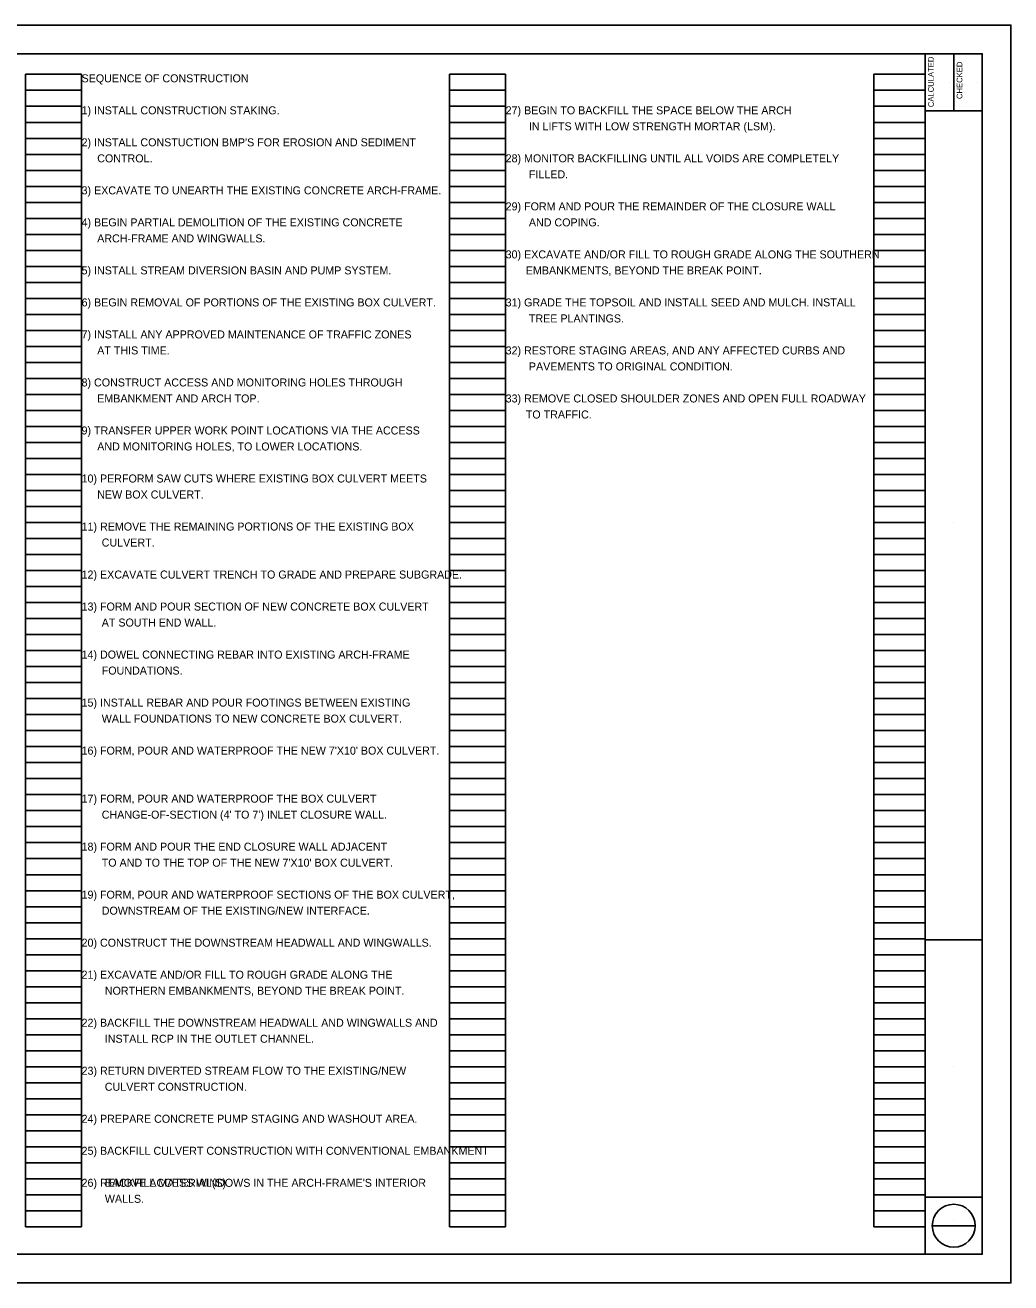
# Model space of a CAD drawing. Extents: x 0 to 55.9, y -18.9 to 33.1.
# Drawn here: x 16.75 to 34, y 0 to 22 of the extents above; entities that cross this region are included whole.
import ezdxf

# ---------------------------------------------------------------- set-up
doc = ezdxf.new("R2010")
doc.units = 0
for name, color, linetype in [('SC_Scratch1', 7, 'Continuous'), ('SH_Border', 7, 'Continuous'), ('SH_Cut_Line', 7, 'Continuous'), ('SH_Data', 7, 'Continuous'), ('SH_Text', 7, 'Continuous')]:
    doc.layers.add(name, color=color, linetype=linetype)

msp = doc.modelspace()

# ---------------------------------------------------------------- linework, layer by layer
at = {"layer": 'SC_Scratch1'}
for p, q in [((16.76, 0.98), (16.76, 21.14)), ((16.76, 21.14), (17.74, 21.14)), ((17.74, 0.98), (17.74, 21.14)), ((24.18, 0.98), (24.18, 21.14)), ((24.18, 21.14), (25.16, 21.14)), ((25.16, 0.98), (25.16, 21.14)), ((31.6, 0.98), (31.6, 21.14)), ((31.6, 21.14), (32.5, 21.14)), ((32.5, 0.98), (32.5, 21.14)), ((16.76, 20.86), (17.74, 20.86)), ((24.18, 20.86), (25.16, 20.86)), ((31.6, 20.86), (32.5, 20.86)), ((16.76, 20.58), (17.74, 20.58)), ((24.18, 20.58), (25.16, 20.58)), ((31.6, 20.58), (32.5, 20.58)), ((16.76, 20.3), (17.74, 20.3)), ((24.18, 20.3), (25.16, 20.3)), ((31.6, 20.3), (32.5, 20.3)), ((16.76, 20.02), (17.74, 20.02)), ((24.18, 20.02), (25.16, 20.02)), ((31.6, 20.02), (32.5, 20.02)), ((16.76, 19.74), (17.74, 19.74)), ((24.18, 19.74), (25.16, 19.74)), ((31.6, 19.74), (32.5, 19.74)), ((16.76, 19.46), (17.74, 19.46)), ((24.18, 19.46), (25.16, 19.46)), ((31.6, 19.46), (32.5, 19.46)), ((16.76, 19.18), (17.74, 19.18)), ((24.18, 19.18), (25.16, 19.18)), ((31.6, 19.18), (32.5, 19.18)), ((16.76, 18.9), (17.74, 18.9)), ((24.18, 18.9), (25.16, 18.9)), ((31.6, 18.9), (32.5, 18.9)), ((16.76, 18.62), (17.74, 18.62)), ((24.18, 18.62), (25.16, 18.62)), ((31.6, 18.62), (32.5, 18.62)), ((16.76, 18.34), (17.74, 18.34)), ((24.18, 18.34), (25.16, 18.34)), ((31.6, 18.34), (32.5, 18.34)), ((16.76, 18.06), (17.74, 18.06)), ((24.18, 18.06), (25.16, 18.06)), ((31.6, 18.06), (32.5, 18.06)), ((16.76, 17.78), (17.74, 17.78)), ((24.18, 17.78), (25.16, 17.78)), ((31.6, 17.78), (32.5, 17.78)), ((16.76, 17.5), (17.74, 17.5)), ((24.18, 17.5), (25.16, 17.5)), ((31.6, 17.5), (32.5, 17.5)), ((16.76, 17.22), (17.74, 17.22)), ((24.18, 17.22), (25.16, 17.22)), ((31.6, 17.22), (32.5, 17.22)), ((16.76, 16.94), (17.74, 16.94)), ((24.18, 16.94), (25.16, 16.94)), ((31.6, 16.94), (32.5, 16.94)), ((16.76, 16.66), (17.74, 16.66)), ((24.18, 16.66), (25.16, 16.66)), ((31.6, 16.66), (32.5, 16.66)), ((16.76, 16.38), (17.74, 16.38)), ((24.18, 16.38), (25.16, 16.38)), ((31.6, 16.38), (32.5, 16.38)), ((16.76, 16.1), (17.74, 16.1)), ((24.18, 16.1), (25.16, 16.1)), ((31.6, 16.1), (32.5, 16.1)), ((16.76, 15.82), (17.74, 15.82)), ((24.18, 15.82), (25.16, 15.82)), ((31.6, 15.82), (32.5, 15.82)), ((16.76, 15.54), (17.74, 15.54)), ((24.18, 15.54), (25.16, 15.54)), ((31.6, 15.54), (32.5, 15.54)), ((16.76, 15.26), (17.74, 15.26)), ((24.18, 15.26), (25.16, 15.26)), ((31.6, 15.26), (32.5, 15.26)), ((16.76, 14.98), (17.74, 14.98)), ((24.18, 14.98), (25.16, 14.98)), ((31.6, 14.98), (32.5, 14.98)), ((16.76, 14.7), (17.74, 14.7)), ((24.18, 14.7), (25.16, 14.7)), ((31.6, 14.7), (32.5, 14.7)), ((16.76, 14.42), (17.74, 14.42)), ((24.18, 14.42), (25.16, 14.42)), ((31.6, 14.42), (32.5, 14.42)), ((16.76, 14.14), (17.74, 14.14)), ((24.18, 14.14), (25.16, 14.14)), ((31.6, 14.14), (32.5, 14.14)), ((16.76, 13.86), (17.74, 13.86)), ((24.18, 13.86), (25.16, 13.86)), ((31.6, 13.86), (32.5, 13.86)), ((16.76, 13.58), (17.74, 13.58)), ((24.18, 13.58), (25.16, 13.58)), ((31.6, 13.58), (32.5, 13.58)), ((16.76, 13.3), (17.74, 13.3)), ((24.18, 13.3), (25.16, 13.3)), ((31.6, 13.3), (32.5, 13.3)), ((16.76, 13.02), (17.74, 13.02)), ((24.18, 13.02), (25.16, 13.02)), ((31.6, 13.02), (32.5, 13.02)), ((16.76, 12.74), (17.74, 12.74)), ((24.18, 12.74), (25.16, 12.74)), ((31.6, 12.74), (32.5, 12.74)), ((16.76, 12.46), (17.74, 12.46)), ((24.18, 12.46), (25.16, 12.46)), ((31.6, 12.46), (32.5, 12.46)), ((16.76, 12.18), (17.74, 12.18)), ((24.18, 12.18), (25.16, 12.18)), ((31.6, 12.18), (32.5, 12.18)), ((16.76, 11.9), (17.74, 11.9)), ((24.18, 11.9), (25.16, 11.9)), ((31.6, 11.9), (32.5, 11.9)), ((16.76, 11.62), (17.74, 11.62)), ((24.18, 11.62), (25.16, 11.62)), ((31.6, 11.62), (32.5, 11.62)), ((16.76, 11.34), (17.74, 11.34)), ((24.18, 11.34), (25.16, 11.34)), ((31.6, 11.34), (32.5, 11.34)), ((16.76, 11.06), (17.74, 11.06)), ((24.18, 11.06), (25.16, 11.06)), ((31.6, 11.06), (32.5, 11.06)), ((16.76, 10.78), (17.74, 10.78)), ((24.18, 10.78), (25.16, 10.78)), ((31.6, 10.78), (32.5, 10.78)), ((16.76, 10.5), (17.74, 10.5)), ((24.18, 10.5), (25.16, 10.5)), ((31.6, 10.5), (32.5, 10.5)), ((16.76, 10.22), (17.74, 10.22)), ((24.18, 10.22), (25.16, 10.22)), ((31.6, 10.22), (32.5, 10.22)), ((16.76, 9.94), (17.74, 9.94)), ((24.18, 9.94), (25.16, 9.94)), ((31.6, 9.94), (32.5, 9.94)), ((16.76, 9.66), (17.74, 9.66)), ((24.18, 9.66), (25.16, 9.66)), ((31.6, 9.66), (32.5, 9.66)), ((16.76, 9.38), (17.74, 9.38)), ((24.18, 9.38), (25.16, 9.38)), ((31.6, 9.38), (32.5, 9.38)), ((16.76, 9.1), (17.74, 9.1)), ((24.18, 9.1), (25.16, 9.1)), ((31.6, 9.1), (32.5, 9.1)), ((16.76, 8.82), (17.74, 8.82)), ((24.18, 8.82), (25.16, 8.82)), ((31.6, 8.82), (32.5, 8.82)), ((16.76, 8.54), (17.74, 8.54)), ((24.18, 8.54), (25.16, 8.54)), ((31.6, 8.54), (32.5, 8.54)), ((16.76, 8.26), (17.74, 8.26)), ((24.18, 8.26), (25.16, 8.26)), ((31.6, 8.26), (32.5, 8.26)), ((16.76, 7.98), (17.74, 7.98)), ((24.18, 7.98), (25.16, 7.98)), ((31.6, 7.98), (32.5, 7.98)), ((16.76, 7.7), (17.74, 7.7)), ((24.18, 7.7), (25.16, 7.7)), ((31.6, 7.7), (32.5, 7.7)), ((16.76, 7.42), (17.74, 7.42)), ((24.18, 7.42), (25.16, 7.42)), ((31.6, 7.42), (32.5, 7.42)), ((16.76, 7.14), (17.74, 7.14)), ((24.18, 7.14), (25.16, 7.14)), ((31.6, 7.14), (32.5, 7.14)), ((16.76, 6.86), (17.74, 6.86)), ((24.18, 6.86), (25.16, 6.86)), ((31.6, 6.86), (32.5, 6.86)), ((16.76, 6.58), (17.74, 6.58)), ((24.18, 6.58), (25.16, 6.58)), ((31.6, 6.58), (32.5, 6.58)), ((16.76, 6.3), (17.74, 6.3)), ((24.18, 6.3), (25.16, 6.3)), ((31.6, 6.3), (32.5, 6.3)), ((16.76, 6.02), (17.74, 6.02)), ((24.18, 6.02), (25.16, 6.02)), ((31.6, 6.02), (32.5, 6.02)), ((16.76, 5.74), (17.74, 5.74)), ((24.18, 5.74), (25.16, 5.74)), ((31.6, 5.74), (32.5, 5.74)), ((16.76, 5.46), (17.74, 5.46)), ((24.18, 5.46), (25.16, 5.46)), ((31.6, 5.46), (32.5, 5.46)), ((16.76, 5.18), (17.74, 5.18)), ((24.18, 5.18), (25.16, 5.18)), ((31.6, 5.18), (32.5, 5.18)), ((16.76, 4.9), (17.74, 4.9)), ((24.18, 4.9), (25.16, 4.9)), ((31.6, 4.9), (32.5, 4.9)), ((16.76, 4.62), (17.74, 4.62)), ((24.18, 4.62), (25.16, 4.62)), ((31.6, 4.62), (32.5, 4.62)), ((16.76, 4.34), (17.74, 4.34)), ((24.18, 4.34), (25.16, 4.34)), ((31.6, 4.34), (32.5, 4.34)), ((16.76, 4.06), (17.74, 4.06)), ((24.18, 4.06), (25.16, 4.06)), ((31.6, 4.06), (32.5, 4.06)), ((16.76, 3.78), (17.74, 3.78)), ((24.18, 3.78), (25.16, 3.78)), ((31.6, 3.78), (32.5, 3.78)), ((16.76, 3.5), (17.74, 3.5)), ((24.18, 3.5), (25.16, 3.5)), ((31.6, 3.5), (32.5, 3.5)), ((16.76, 3.22), (17.74, 3.22)), ((24.18, 3.22), (25.16, 3.22)), ((31.6, 3.22), (32.5, 3.22)), ((16.76, 2.94), (17.74, 2.94)), ((24.18, 2.94), (25.16, 2.94)), ((31.6, 2.94), (32.5, 2.94)), ((16.76, 2.66), (17.74, 2.66)), ((24.18, 2.66), (25.16, 2.66)), ((31.6, 2.66), (32.5, 2.66)), ((16.76, 2.38), (17.74, 2.38)), ((24.18, 2.38), (25.16, 2.38)), ((31.6, 2.38), (32.5, 2.38)), ((16.76, 2.1), (17.74, 2.1)), ((24.18, 2.1), (25.16, 2.1)), ((31.6, 2.1), (32.5, 2.1)), ((16.76, 1.82), (17.74, 1.82)), ((24.18, 1.82), (25.16, 1.82)), ((31.6, 1.82), (32.5, 1.82)), ((16.76, 1.54), (17.74, 1.54)), ((24.18, 1.54), (25.16, 1.54)), ((31.6, 1.54), (32.5, 1.54)), ((16.76, 1.26), (17.74, 1.26)), ((24.18, 1.26), (25.16, 1.26)), ((31.6, 1.26), (32.5, 1.26)), ((16.76, 0.98), (17.74, 0.98)), ((24.18, 0.98), (25.16, 0.98)), ((31.6, 0.98), (32.5, 0.98))]:
    msp.add_line(p, q, dxfattribs=at)
at = {"layer": 'SH_Border'}
for p, q in [((32.5, 0.5), (32.5, 21.5)), ((33, 21.5), (33, 20.5)), ((32.5, 20.5), (33.5, 20.5)), ((32.5, 6), (33.5, 6)), ((32.5, 1.5), (33.5, 1.5))]:
    msp.add_line(p, q, dxfattribs=at)
msp.add_lwpolyline([(2, 21.5), (33.5, 21.5), (33.5, 0.5), (2, 0.5)], close=True, dxfattribs=at)
at = {"layer": 'SH_Cut_Line'}
msp.add_lwpolyline([(0, 0), (34, 0), (34, 22), (0, 22)], close=True, dxfattribs=at)
at = {"layer": 'SH_Data'}
for p, q in [((32.92, 21.004), (32.92, 21.004)), ((33.42, 21.004), (33.42, 21.004)), ((33, 13.292), (33, 13.292)), ((33, 3.792), (33, 3.792)), ((32.625, 1), (33.375, 1)), ((33, 1.085), (33, 1.085)), ((33, 0.745), (33, 0.745))]:
    msp.add_line(p, q, dxfattribs=at)
msp.add_circle((33, 1), 0.375, dxfattribs=at)

# ---------------------------------------------------------------- texts
for s, p in [('CALCULATED', (32.652, 20.565)), ('CHECKED', (33.152, 20.708))]:
    msp.add_text(s, height=0.1, rotation=90, dxfattribs=at).set_placement(p)
at = {"layer": 'SH_Text'}
for s, p in [('SEQUENCE OF CONSTRUCTION', (17.74, 21)), ('1) INSTALL CONSTRUCTION STAKING.', (17.74, 20.44)), ('27) BEGIN TO BACKFILL THE SPACE BELOW THE ARCH', (25.16, 20.44)), ('IN LIFTS WITH LOW STRENGTH MORTAR (LSM).', (25.567, 20.16)), ("2) INSTALL CONSTUCTION BMP'S FOR EROSION AND SEDIMENT ", (17.74, 19.88)), ('CONTROL.', (18.014, 19.6)), ('28) MONITOR BACKFILLING UNTIL ALL VOIDS ARE COMPLETELY ', (25.16, 19.6)), ('FILLED.', (25.567, 19.32)), ('3) EXCAVATE TO UNEARTH THE EXISTING CONCRETE ARCH-FRAME.', (17.74, 19.04)), ('29) FORM AND POUR THE REMAINDER OF THE CLOSURE WALL', (25.16, 18.76)), ('4) BEGIN PARTIAL DEMOLITION OF THE EXISTING CONCRETE', (17.74, 18.48)), ('AND COPING.', (25.567, 18.48)), ('ARCH-FRAME AND WINGWALLS.', (18.014, 18.2)), ('30) EXCAVATE AND/OR FILL TO ROUGH GRADE ALONG THE SOUTHERN ', (25.16, 17.92)), ('5) INSTALL STREAM DIVERSION BASIN AND PUMP SYSTEM.', (17.74, 17.64)), ('EMBANKMENTS, BEYOND THE BREAK POINT.', (25.513, 17.64)), ('6) BEGIN REMOVAL OF PORTIONS OF THE EXISTING BOX CULVERT.', (17.74, 17.08)), ('31) GRADE THE TOPSOIL AND INSTALL SEED AND MULCH. INSTALL', (25.16, 17.08)), ('TREE PLANTINGS.', (25.567, 16.8)), ('7) INSTALL ANY APPROVED MAINTENANCE OF TRAFFIC ZONES', (17.74, 16.52)), ('AT THIS TIME.', (18.014, 16.24)), ('32) RESTORE STAGING AREAS, AND ANY AFFECTED CURBS AND', (25.16, 16.24)), ('PAVEMENTS TO ORIGINAL CONDITION.', (25.567, 15.96)), ('8) CONSTRUCT ACCESS AND MONITORING HOLES THROUGH ', (17.74, 15.68)), ('EMBANKMENT AND ARCH TOP.', (18.014, 15.4)), ('33) REMOVE CLOSED SHOULDER ZONES AND OPEN FULL ROADWAY', (25.16, 15.4)), ('TO TRAFFIC.', (25.513, 15.12)), ('9) TRANSFER UPPER WORK POINT LOCATIONS VIA THE ACCESS', (17.74, 14.84)), ('AND MONITORING HOLES, TO LOWER LOCATIONS.', (18.014, 14.56)), ('10) PERFORM SAW CUTS WHERE EXISTING BOX CULVERT MEETS', (17.74, 14)), ('NEW BOX CULVERT.', (18.014, 13.72)), ('11) REMOVE THE REMAINING PORTIONS OF THE EXISTING BOX ', (17.74, 13.16)), ('CULVERT.', (18.093, 12.88)), ('12) EXCAVATE CULVERT TRENCH TO GRADE AND PREPARE SUBGRADE.', (17.74, 12.32)), ('13) FORM AND POUR SECTION OF NEW CONCRETE BOX CULVERT', (17.74, 11.76)), ('AT SOUTH END WALL.', (18.093, 11.48)), ('14) DOWEL CONNECTING REBAR INTO EXISTING ARCH-FRAME', (17.74, 10.92)), ('FOUNDATIONS.', (18.093, 10.64)), ('15) INSTALL REBAR AND POUR FOOTINGS BETWEEN EXISTING', (17.74, 10.08)), ('WALL FOUNDATIONS TO NEW CONCRETE BOX CULVERT.', (18.093, 9.8)), ("16) FORM, POUR AND WATERPROOF THE NEW 7'X10' BOX CULVERT.", (17.74, 9.24)), ('17) FORM, POUR AND WATERPROOF THE BOX CULVERT ', (17.74, 8.4)), ("CHANGE-OF-SECTION (4' TO 7') INLET CLOSURE WALL.", (18.093, 8.12)), ('18) FORM AND POUR THE END CLOSURE WALL ADJACENT', (17.74, 7.56)), ("TO AND TO THE TOP OF THE NEW 7'X10' BOX CULVERT.", (18.093, 7.28)), ('19) FORM, POUR AND WATERPROOF SECTIONS OF THE BOX CULVERT,', (17.74, 6.72)), ('DOWNSTREAM OF THE EXISTING/NEW INTERFACE.', (18.093, 6.44)), ('20) CONSTRUCT THE DOWNSTREAM HEADWALL AND WINGWALLS.', (17.74, 5.88)), ('21) EXCAVATE AND/OR FILL TO ROUGH GRADE ALONG THE ', (17.74, 5.32)), ('NORTHERN EMBANKMENTS, BEYOND THE BREAK POINT.', (18.147, 5.04)), ('22) BACKFILL THE DOWNSTREAM HEADWALL AND WINGWALLS AND', (17.74, 4.48)), ('INSTALL RCP IN THE OUTLET CHANNEL.', (18.147, 4.2)), ('23) RETURN DIVERTED STREAM FLOW TO THE EXISTING/NEW ', (17.74, 3.64)), ('CULVERT CONSTRUCTION.', (18.147, 3.36)), ('24) PREPARE CONCRETE PUMP STAGING AND WASHOUT AREA.', (17.74, 2.8)), ('25) BACKFILL CULVERT CONSTRUCTION WITH CONVENTIONAL EMBANKMENT', (17.74, 2.24)), ("26) REMOVE ACCESS WINDOWS IN THE ARCH-FRAME'S INTERIOR", (17.74, 1.68)), ('BACKFILL MATERIAL(S).', (18.147, 1.68)), ('WALLS.', (18.147, 1.4))]:
    msp.add_text(s, height=0.14, dxfattribs=at).set_placement(p)

doc.saveas('drawing.dxf')
